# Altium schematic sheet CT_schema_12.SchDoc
size 391 x 278 mm
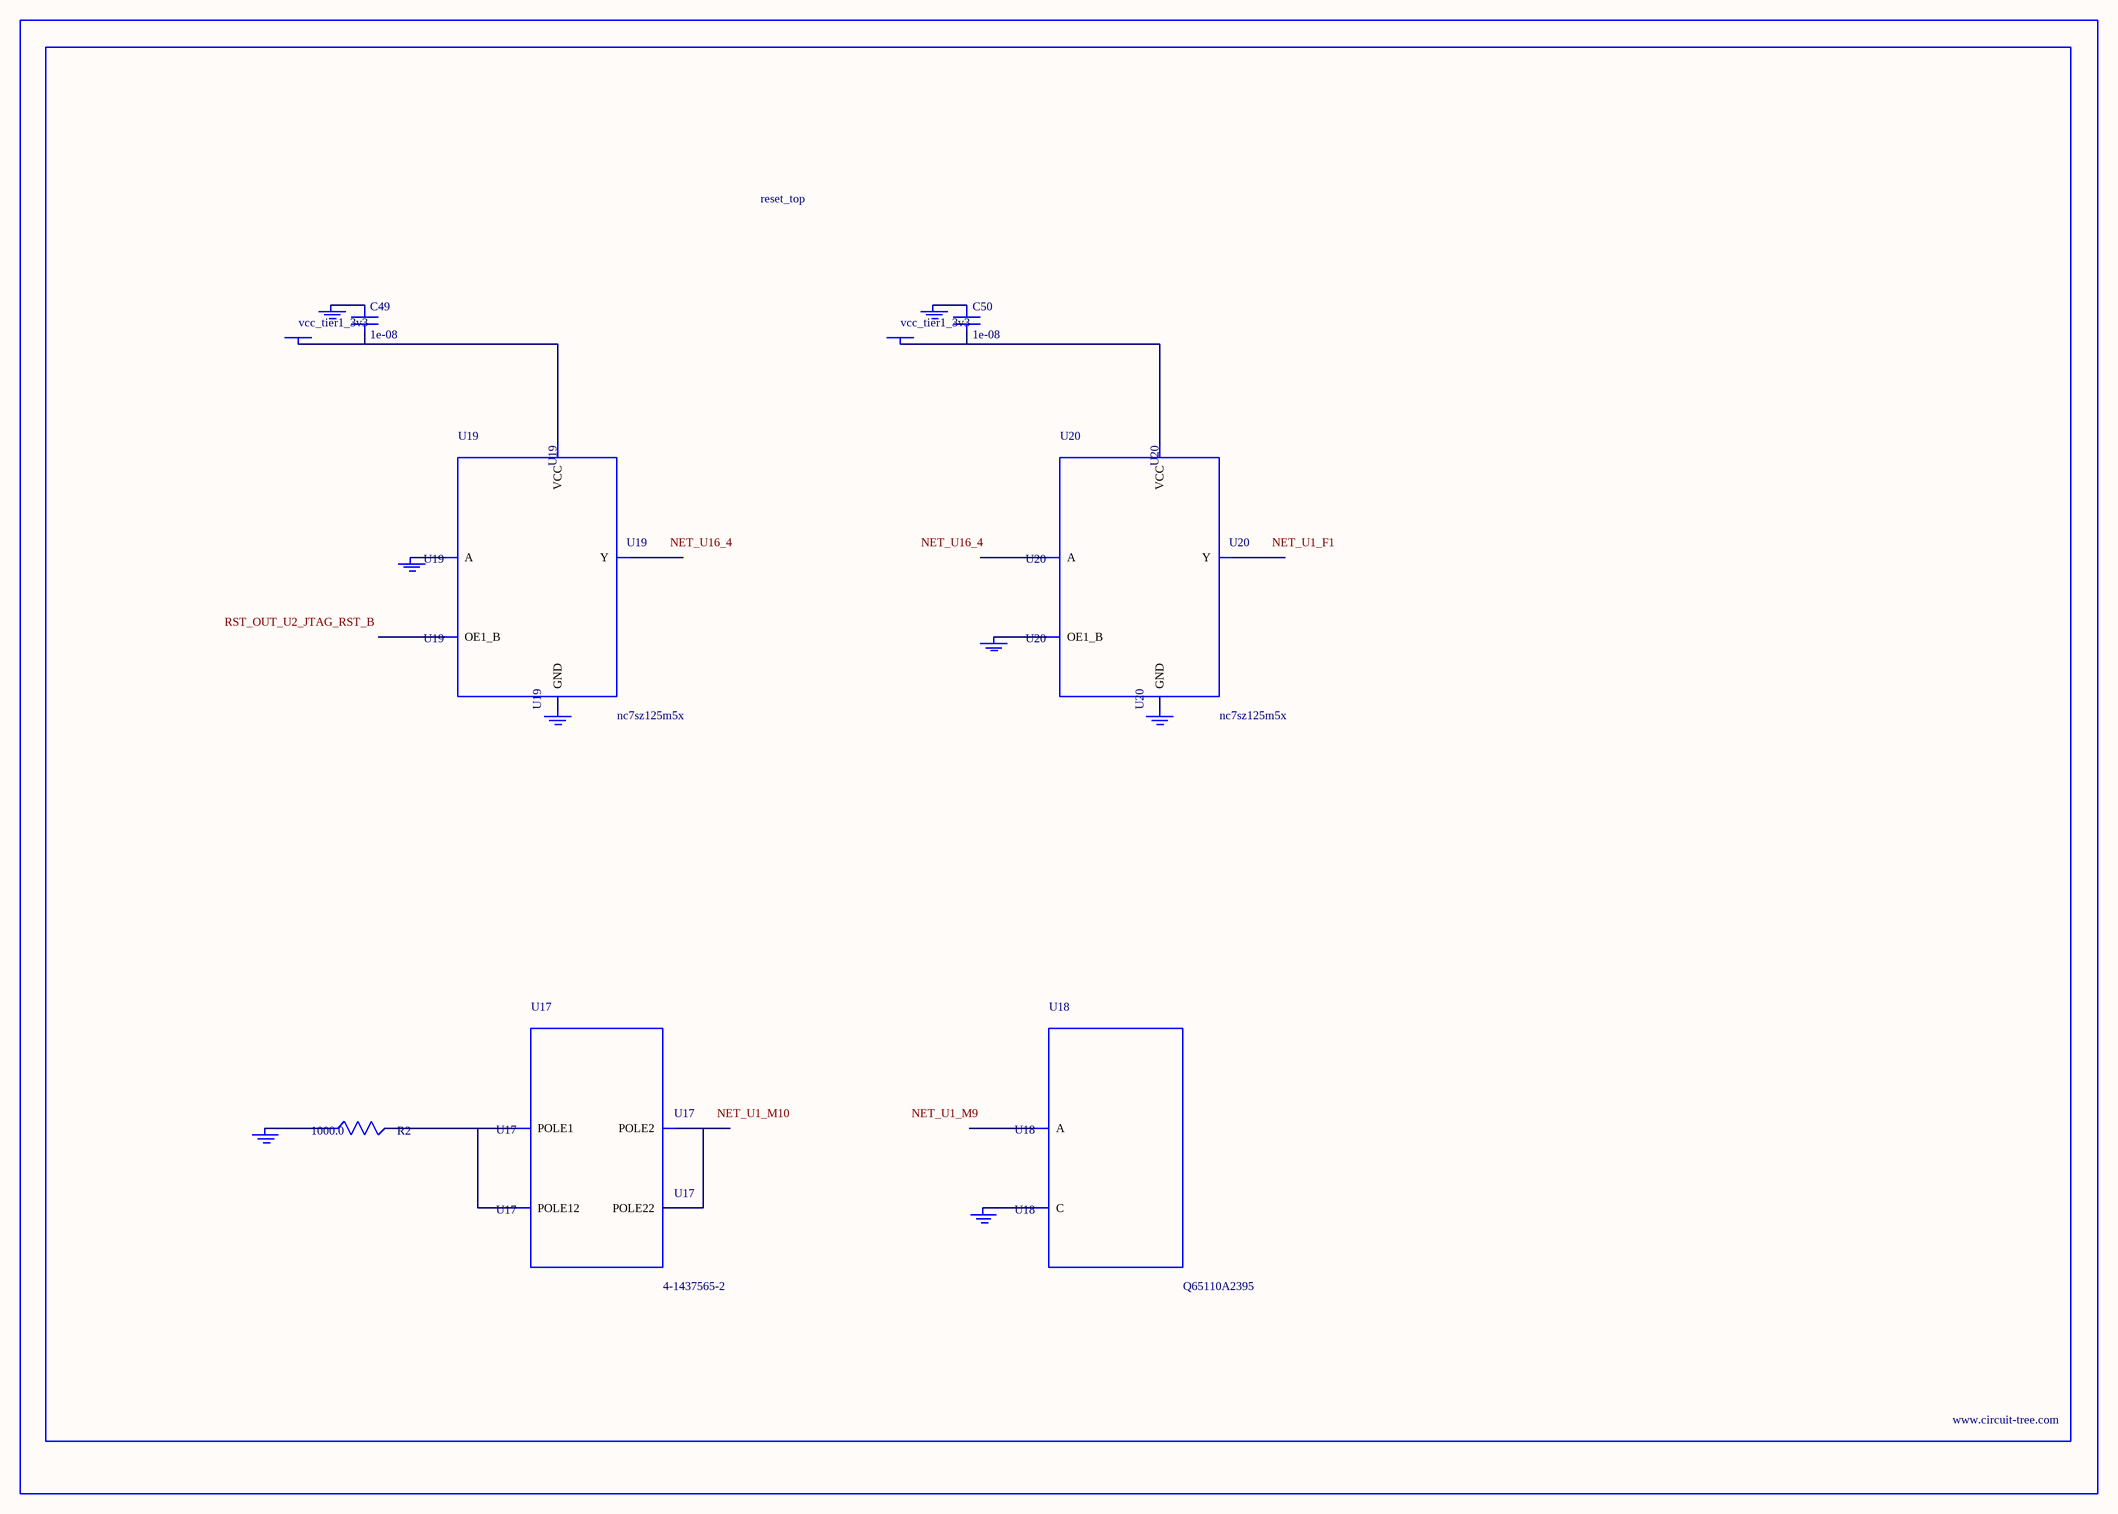
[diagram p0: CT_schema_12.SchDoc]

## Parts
BORDER11  (no value)
C49  1e-08  [C0402]
C50  1e-08  [C0402]
GND_INSTANCE_11_0  (no value)
GND_INSTANCE_11_1  (no value)
GND_INSTANCE_11_2  (no value)
GND_INSTANCE_11_3  (no value)
GND_INSTANCE_11_4  (no value)
GND_INSTANCE_11_5  (no value)
GND_INSTANCE_11_6  (no value)
GND_INSTANCE_11_7  (no value)
POWER_INSTANCE_11_0  vcc_tier1_3v3
POWER_INSTANCE_11_1  vcc_tier1_3v3
R2  1000.0  [R0603]
U17  4-1437565-2  [SW_4-1437565-2]
U18  Q65110A2395  [LGM67K-G1J2-24-Z]
U19  nc7sz125m5x  [NC7SZ125M5X]
U20  nc7sz125m5x  [NC7SZ125M5X]

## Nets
NetC49_1: C49.1 GND_INSTANCE_11_2.0(GND)
NetC49_2: C49.2 POWER_INSTANCE_11_0.0(PWR) U19.5(VCC)
NetC50_1: C50.1 GND_INSTANCE_11_5.0(GND)
NetC50_2: C50.2 POWER_INSTANCE_11_1.0(PWR) U20.5(VCC)
NetGND_INSTANCE_11_0_0: GND_INSTANCE_11_0.0(GND) R2.1
NetGND_INSTANCE_11_1_0: GND_INSTANCE_11_1.0(GND) U18.C
NetGND_INSTANCE_11_3_0: GND_INSTANCE_11_3.0(GND) U19.2(A)
NetGND_INSTANCE_11_4_0: GND_INSTANCE_11_4.0(GND) U19.3(GND)
NetGND_INSTANCE_11_6_0: GND_INSTANCE_11_6.0(GND) U20.1(OE1_B)
NetGND_INSTANCE_11_7_0: GND_INSTANCE_11_7.0(GND) U20.3(GND)
NetR2_2: R2.2 U17.1(POLE1) U17.2(POLE12)
NetU17_3: U17.3(POLE2) U17.4(POLE22)

Not connected (* = marked no-connect by the designer): U18 A; U19 1(OE1_B) 4(Y); U20 2(A) 4(Y)

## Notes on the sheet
- Labels drawn without touching a wire or pin: NET_U1_F1, NET_U1_M9, NET_U1_M10, NET_U16_4, RST_OUT_U2_JTAG_RST_B

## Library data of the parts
BORDER11 = BORDER_PAGE11
C49 C50 = C0402C103K3RAC
GND_INSTANCE_11_0-GND_INSTANCE_11_7 = GND
POWER_INSTANCE_11_0 POWER_INSTANCE_11_1 = PWR
R2 = RC0603JR-071KL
